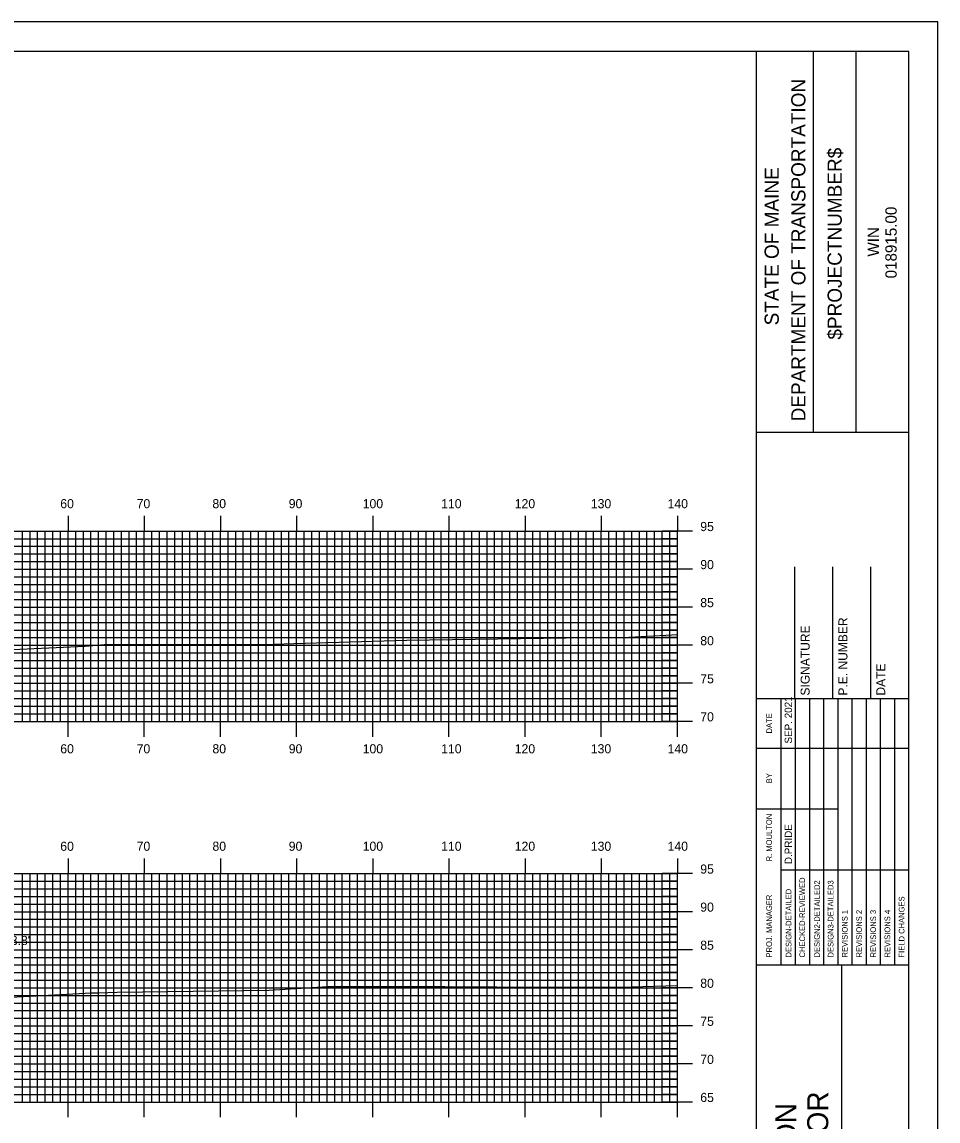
# Model space of a CAD drawing. Extents: x 1776744 to 1777088, y 442591 to 442811.
# Drawn here: x 1776964.2 to 1777084.5, y 442666.2 to 442810.5 of the extents above; entities that cross this region are included whole.
import ezdxf

# ---------------------------------------------------------------- set-up
doc = ezdxf.new("R2010")
doc.units = 0
for name, color, linetype in [('BORDER', 7, 'Continuous'), ('D_Text_Standard', 7, 'Continuous'), ('H_V ANNOTATION', 7, 'Continuous'), ('MAJOR', 7, 'Continuous'), ('MINOR', 7, 'Continuous'), ('PLOT BOUNDARY', 7, 'Continuous'), ('S_Roadway_Centerline', 7, 'Continuous')]:
    doc.layers.add(name, color=color, linetype=linetype)

msp = doc.modelspace()

# ---------------------------------------------------------------- linework, layer by layer
at = {"layer": 'BORDER'}
for p, q in [((1777060.65, 442596.67), (1777060.65, 442806.67)), ((1777068.11, 442756.66), (1777068.11, 442806.66)), ((1777073.7, 442756.66), (1777073.7, 442806.66)), ((1777060.65, 442756.65), (1777080.65, 442756.65)), ((1777065.65, 442721.67), (1777065.65, 442738.97)), ((1777070.65, 442721.67), (1777070.65, 442738.97)), ((1777075.65, 442721.67), (1777075.65, 442738.97)), ((1777060.65, 442721.67), (1777080.65, 442721.67)), ((1777060.65, 442686.67), (1777080.65, 442686.67)), ((1777071.83, 442616.67), (1777071.83, 442686.67))]:
    msp.add_line(p, q, dxfattribs=at)
msp.add_lwpolyline([(1776760.65, 442596.67), (1777080.65, 442596.67), (1777080.65, 442806.67), (1776760.65, 442806.67)], close=True, dxfattribs=at)
for points in [[(1777063.88, 442715.17), (1777063.88, 442721.67)], [(1777065.75, 442686.68), (1777065.75, 442721.67)], [(1777067.61, 442721.67), (1777067.61, 442686.68)], [(1777069.47, 442686.68), (1777069.47, 442721.67)], [(1777071.34, 442686.68), (1777071.34, 442721.67)], [(1777073.2, 442686.68), (1777073.2, 442721.67)], [(1777075.06, 442686.68), (1777075.06, 442721.67)], [(1777076.93, 442686.68), (1777076.93, 442721.67)], [(1777078.79, 442686.68), (1777078.79, 442721.67)], [(1777063.88, 442686.68), (1777063.88, 442720.26)], [(1777060.65, 442715.17), (1777080.65, 442715.17)], [(1777060.65, 442707.17), (1777063.88, 442707.17)], [(1777063.88, 442707.17), (1777071.33, 442707.17)], [(1777063.88, 442699.17), (1777080.65, 442699.17)]]:
    msp.add_lwpolyline(points, dxfattribs=at)
at = {"layer": 'MAJOR'}
for p, q in [((1776970.25, 442745.67), (1776970.25, 442743.67)), ((1776980.25, 442745.67), (1776980.25, 442743.67)), ((1776990.25, 442745.67), (1776990.25, 442743.67)), ((1777000.25, 442745.67), (1777000.25, 442743.67)), ((1777010.25, 442745.67), (1777010.25, 442743.67)), ((1777020.25, 442745.67), (1777020.25, 442743.67)), ((1777030.25, 442745.67), (1777030.25, 442743.67)), ((1777040.25, 442745.67), (1777040.25, 442743.67)), ((1777050.25, 442745.67), (1777050.25, 442743.67)), ((1776770.25, 442743.67), (1777050.25, 442743.67)), ((1776770.25, 442743.67), (1777050.25, 442743.67)), ((1776970.25, 442718.67), (1776970.25, 442743.67)), ((1776980.25, 442718.67), (1776980.25, 442743.67)), ((1776990.25, 442718.67), (1776990.25, 442743.67)), ((1777000.25, 442718.67), (1777000.25, 442743.67)), ((1777010.25, 442718.67), (1777010.25, 442743.67)), ((1777020.25, 442718.67), (1777020.25, 442743.67)), ((1777030.25, 442718.67), (1777030.25, 442743.67)), ((1777040.25, 442718.67), (1777040.25, 442743.67)), ((1777052.25, 442743.67), (1777048.25, 442743.67)), ((1777050.25, 442718.67), (1777050.25, 442743.67)), ((1777050.25, 442718.67), (1777050.25, 442743.67)), ((1776770.25, 442738.67), (1777050.25, 442738.67)), ((1777052.25, 442738.67), (1777048.25, 442738.67)), ((1776770.25, 442733.67), (1777050.25, 442733.67)), ((1777052.25, 442733.67), (1777048.25, 442733.67)), ((1776770.25, 442728.67), (1777050.25, 442728.67)), ((1777052.25, 442728.67), (1777048.25, 442728.67)), ((1776770.25, 442723.67), (1777050.25, 442723.67)), ((1777052.25, 442723.67), (1777048.25, 442723.67)), ((1776770.25, 442718.67), (1777050.25, 442718.67)), ((1776770.25, 442718.67), (1777050.25, 442718.67)), ((1776970.25, 442716.66), (1776970.25, 442718.67)), ((1776980.25, 442716.66), (1776980.25, 442718.67)), ((1776990.25, 442716.66), (1776990.25, 442718.67)), ((1777000.25, 442716.66), (1777000.25, 442718.67)), ((1777010.25, 442716.66), (1777010.25, 442718.67)), ((1777020.25, 442716.66), (1777020.25, 442718.67)), ((1777030.25, 442716.66), (1777030.25, 442718.67)), ((1777040.25, 442716.66), (1777040.25, 442718.67)), ((1777052.25, 442718.67), (1777048.25, 442718.67)), ((1777050.25, 442716.66), (1777050.25, 442718.67)), ((1776970.25, 442700.67), (1776970.25, 442698.67)), ((1776980.25, 442700.67), (1776980.25, 442698.67)), ((1776990.25, 442700.67), (1776990.25, 442698.67)), ((1777000.25, 442700.67), (1777000.25, 442698.67)), ((1777010.25, 442700.67), (1777010.25, 442698.67)), ((1777020.25, 442700.67), (1777020.25, 442698.67)), ((1777030.25, 442700.67), (1777030.25, 442698.67)), ((1777040.25, 442700.67), (1777040.25, 442698.67)), ((1777050.25, 442700.67), (1777050.25, 442698.67)), ((1776770.25, 442698.67), (1777050.25, 442698.67)), ((1776770.25, 442698.67), (1777050.25, 442698.67)), ((1776970.25, 442668.67), (1776970.25, 442698.67)), ((1776980.25, 442668.67), (1776980.25, 442698.67)), ((1776990.25, 442668.67), (1776990.25, 442698.67)), ((1777000.25, 442668.67), (1777000.25, 442698.67)), ((1777010.25, 442668.67), (1777010.25, 442698.67)), ((1777020.25, 442668.67), (1777020.25, 442698.67)), ((1777030.25, 442668.67), (1777030.25, 442698.67)), ((1777040.25, 442668.67), (1777040.25, 442698.67)), ((1777052.25, 442698.67), (1777048.25, 442698.67)), ((1777050.25, 442668.67), (1777050.25, 442698.67)), ((1777050.25, 442668.67), (1777050.25, 442698.67)), ((1776770.25, 442693.67), (1777050.25, 442693.67)), ((1777052.25, 442693.67), (1777048.25, 442693.67)), ((1776770.25, 442688.67), (1777050.25, 442688.67)), ((1777052.25, 442688.67), (1777048.25, 442688.67)), ((1776770.25, 442683.67), (1777050.25, 442683.67)), ((1777052.25, 442683.67), (1777048.25, 442683.67)), ((1776770.25, 442678.67), (1777050.25, 442678.67)), ((1777052.25, 442678.67), (1777048.25, 442678.67)), ((1776770.25, 442673.67), (1777050.25, 442673.67)), ((1777052.25, 442673.67), (1777048.25, 442673.67)), ((1776770.25, 442668.67), (1777050.25, 442668.67)), ((1776770.25, 442668.67), (1777050.25, 442668.67)), ((1776970.25, 442666.66), (1776970.25, 442668.67)), ((1776980.25, 442666.66), (1776980.25, 442668.67)), ((1776990.25, 442666.66), (1776990.25, 442668.67)), ((1777000.25, 442666.66), (1777000.25, 442668.67)), ((1777010.25, 442666.66), (1777010.25, 442668.67)), ((1777020.25, 442666.66), (1777020.25, 442668.67)), ((1777030.25, 442666.66), (1777030.25, 442668.67)), ((1777040.25, 442666.66), (1777040.25, 442668.67)), ((1777052.25, 442668.67), (1777048.25, 442668.67)), ((1777050.25, 442666.66), (1777050.25, 442668.67))]:
    msp.add_line(p, q, dxfattribs=at)
at = {"layer": 'MINOR'}
for p, q in [((1776770.25, 442742.67), (1777050.25, 442742.67)), ((1776964.25, 442718.67), (1776964.25, 442743.67)), ((1776965.25, 442718.67), (1776965.25, 442743.67)), ((1776966.25, 442718.67), (1776966.25, 442743.67)), ((1776967.25, 442718.67), (1776967.25, 442743.67)), ((1776968.25, 442718.67), (1776968.25, 442743.67)), ((1776969.25, 442718.67), (1776969.25, 442743.67)), ((1776971.25, 442718.67), (1776971.25, 442743.67)), ((1776972.25, 442718.67), (1776972.25, 442743.67)), ((1776973.25, 442718.67), (1776973.25, 442743.67)), ((1776974.25, 442718.67), (1776974.25, 442743.67)), ((1776975.25, 442718.67), (1776975.25, 442743.67)), ((1776976.25, 442718.67), (1776976.25, 442743.67)), ((1776977.25, 442718.67), (1776977.25, 442743.67)), ((1776978.25, 442718.67), (1776978.25, 442743.67)), ((1776979.25, 442718.67), (1776979.25, 442743.67)), ((1776981.25, 442718.67), (1776981.25, 442743.67)), ((1776982.25, 442718.67), (1776982.25, 442743.67)), ((1776983.25, 442718.67), (1776983.25, 442743.67)), ((1776984.25, 442718.67), (1776984.25, 442743.67)), ((1776985.25, 442718.67), (1776985.25, 442743.67)), ((1776986.25, 442718.67), (1776986.25, 442743.67)), ((1776987.25, 442718.67), (1776987.25, 442743.67)), ((1776988.25, 442718.67), (1776988.25, 442743.67)), ((1776989.25, 442718.67), (1776989.25, 442743.67)), ((1776991.25, 442718.67), (1776991.25, 442743.67)), ((1776992.25, 442718.67), (1776992.25, 442743.67)), ((1776993.25, 442718.67), (1776993.25, 442743.67)), ((1776994.25, 442718.67), (1776994.25, 442743.67)), ((1776995.25, 442718.67), (1776995.25, 442743.67)), ((1776996.25, 442718.67), (1776996.25, 442743.67)), ((1776997.25, 442718.67), (1776997.25, 442743.67)), ((1776998.25, 442718.67), (1776998.25, 442743.67)), ((1776999.25, 442718.67), (1776999.25, 442743.67)), ((1777001.25, 442718.67), (1777001.25, 442743.67)), ((1777002.25, 442718.67), (1777002.25, 442743.67)), ((1777003.25, 442718.67), (1777003.25, 442743.67)), ((1777004.25, 442718.67), (1777004.25, 442743.67)), ((1777005.25, 442718.67), (1777005.25, 442743.67)), ((1777006.25, 442718.67), (1777006.25, 442743.67)), ((1777007.25, 442718.67), (1777007.25, 442743.67)), ((1777008.25, 442718.67), (1777008.25, 442743.67)), ((1777009.25, 442718.67), (1777009.25, 442743.67)), ((1777011.25, 442718.67), (1777011.25, 442743.67)), ((1777012.25, 442718.67), (1777012.25, 442743.67)), ((1777013.25, 442718.67), (1777013.25, 442743.67)), ((1777014.25, 442718.67), (1777014.25, 442743.67)), ((1777015.25, 442718.67), (1777015.25, 442743.67)), ((1777016.25, 442718.67), (1777016.25, 442743.67)), ((1777017.25, 442718.67), (1777017.25, 442743.67)), ((1777018.25, 442718.67), (1777018.25, 442743.67)), ((1777019.25, 442718.67), (1777019.25, 442743.67)), ((1777021.25, 442718.67), (1777021.25, 442743.67)), ((1777022.25, 442718.67), (1777022.25, 442743.67)), ((1777023.25, 442718.67), (1777023.25, 442743.67)), ((1777024.25, 442718.67), (1777024.25, 442743.67)), ((1777025.25, 442718.67), (1777025.25, 442743.67)), ((1777026.25, 442718.67), (1777026.25, 442743.67)), ((1777027.25, 442718.67), (1777027.25, 442743.67)), ((1777028.25, 442718.67), (1777028.25, 442743.67)), ((1777029.25, 442718.67), (1777029.25, 442743.67)), ((1777031.25, 442718.67), (1777031.25, 442743.67)), ((1777032.25, 442718.67), (1777032.25, 442743.67)), ((1777033.25, 442718.67), (1777033.25, 442743.67)), ((1777034.25, 442718.67), (1777034.25, 442743.67)), ((1777035.25, 442718.67), (1777035.25, 442743.67)), ((1777036.25, 442718.67), (1777036.25, 442743.67)), ((1777037.25, 442718.67), (1777037.25, 442743.67)), ((1777038.25, 442718.67), (1777038.25, 442743.67)), ((1777039.25, 442718.67), (1777039.25, 442743.67)), ((1777041.25, 442718.67), (1777041.25, 442743.67)), ((1777042.25, 442718.67), (1777042.25, 442743.67)), ((1777043.25, 442718.67), (1777043.25, 442743.67)), ((1777044.25, 442718.67), (1777044.25, 442743.67)), ((1777045.25, 442718.67), (1777045.25, 442743.67)), ((1777046.25, 442718.67), (1777046.25, 442743.67)), ((1777047.25, 442718.67), (1777047.25, 442743.67)), ((1777048.25, 442718.67), (1777048.25, 442743.67)), ((1777050.25, 442742.67), (1777048.25, 442742.67)), ((1777049.25, 442718.67), (1777049.25, 442743.67)), ((1776770.25, 442741.67), (1777050.25, 442741.67)), ((1777050.25, 442741.67), (1777048.25, 442741.67)), ((1776770.25, 442740.67), (1777050.25, 442740.67)), ((1777050.25, 442740.67), (1777048.25, 442740.67)), ((1776770.25, 442739.67), (1777050.25, 442739.67)), ((1777050.25, 442739.67), (1777048.25, 442739.67)), ((1776770.25, 442737.67), (1777050.25, 442737.67)), ((1777050.25, 442737.67), (1777048.25, 442737.67)), ((1776770.25, 442736.67), (1777050.25, 442736.67)), ((1776770.25, 442735.67), (1777050.25, 442735.67)), ((1777050.25, 442736.67), (1777048.25, 442736.67)), ((1777050.25, 442735.67), (1777048.25, 442735.67)), ((1776770.25, 442734.67), (1777050.25, 442734.67)), ((1777050.25, 442734.67), (1777048.25, 442734.67)), ((1776770.25, 442732.67), (1777050.25, 442732.67)), ((1777050.25, 442732.67), (1777048.25, 442732.67)), ((1776770.25, 442731.67), (1777050.25, 442731.67)), ((1777050.25, 442731.67), (1777048.25, 442731.67)), ((1776770.25, 442730.67), (1777050.25, 442730.67)), ((1776770.25, 442729.67), (1777050.25, 442729.67)), ((1777050.25, 442730.67), (1777048.25, 442730.67)), ((1777050.25, 442729.67), (1777048.25, 442729.67)), ((1776770.25, 442727.67), (1777050.25, 442727.67)), ((1777050.25, 442727.67), (1777048.25, 442727.67)), ((1776770.25, 442726.67), (1777050.25, 442726.67)), ((1776770.25, 442725.67), (1777050.25, 442725.67)), ((1777050.25, 442726.67), (1777048.25, 442726.67)), ((1777050.25, 442725.67), (1777048.25, 442725.67)), ((1776770.25, 442724.67), (1777050.25, 442724.67)), ((1777050.25, 442724.67), (1777048.25, 442724.67)), ((1776770.25, 442722.67), (1777050.25, 442722.67)), ((1777050.25, 442722.67), (1777048.25, 442722.67)), ((1776770.25, 442721.67), (1777050.25, 442721.67)), ((1777050.25, 442721.67), (1777048.25, 442721.67)), ((1776770.25, 442720.67), (1777050.25, 442720.67)), ((1776770.25, 442719.67), (1777050.25, 442719.67)), ((1777050.25, 442720.67), (1777048.25, 442720.67)), ((1777050.25, 442719.67), (1777048.25, 442719.67)), ((1776964.25, 442668.67), (1776964.25, 442698.67)), ((1776965.25, 442668.67), (1776965.25, 442698.67)), ((1776966.25, 442668.67), (1776966.25, 442698.67)), ((1776967.25, 442668.67), (1776967.25, 442698.67)), ((1776968.25, 442668.67), (1776968.25, 442698.67)), ((1776969.25, 442668.67), (1776969.25, 442698.67)), ((1776971.25, 442668.67), (1776971.25, 442698.67)), ((1776972.25, 442668.67), (1776972.25, 442698.67)), ((1776973.25, 442668.67), (1776973.25, 442698.67)), ((1776974.25, 442668.67), (1776974.25, 442698.67)), ((1776975.25, 442668.67), (1776975.25, 442698.67)), ((1776976.25, 442668.67), (1776976.25, 442698.67)), ((1776977.25, 442668.67), (1776977.25, 442698.67)), ((1776978.25, 442668.67), (1776978.25, 442698.67)), ((1776979.25, 442668.67), (1776979.25, 442698.67)), ((1776981.25, 442668.67), (1776981.25, 442698.67)), ((1776982.25, 442668.67), (1776982.25, 442698.67)), ((1776983.25, 442668.67), (1776983.25, 442698.67)), ((1776984.25, 442668.67), (1776984.25, 442698.67)), ((1776985.25, 442668.67), (1776985.25, 442698.67)), ((1776986.25, 442668.67), (1776986.25, 442698.67)), ((1776987.25, 442668.67), (1776987.25, 442698.67)), ((1776988.25, 442668.67), (1776988.25, 442698.67)), ((1776989.25, 442668.67), (1776989.25, 442698.67)), ((1776991.25, 442668.67), (1776991.25, 442698.67)), ((1776992.25, 442668.67), (1776992.25, 442698.67)), ((1776993.25, 442668.67), (1776993.25, 442698.67)), ((1776994.25, 442668.67), (1776994.25, 442698.67)), ((1776995.25, 442668.67), (1776995.25, 442698.67)), ((1776996.25, 442668.67), (1776996.25, 442698.67)), ((1776997.25, 442668.67), (1776997.25, 442698.67)), ((1776998.25, 442668.67), (1776998.25, 442698.67)), ((1776999.25, 442668.67), (1776999.25, 442698.67)), ((1777001.25, 442668.67), (1777001.25, 442698.67)), ((1777002.25, 442668.67), (1777002.25, 442698.67)), ((1777003.25, 442668.67), (1777003.25, 442698.67)), ((1777004.25, 442668.67), (1777004.25, 442698.67)), ((1777005.25, 442668.67), (1777005.25, 442698.67)), ((1777006.25, 442668.67), (1777006.25, 442698.67)), ((1777007.25, 442668.67), (1777007.25, 442698.67)), ((1777008.25, 442668.67), (1777008.25, 442698.67)), ((1777009.25, 442668.67), (1777009.25, 442698.67)), ((1777011.25, 442668.67), (1777011.25, 442698.67)), ((1777012.25, 442668.67), (1777012.25, 442698.67)), ((1777013.25, 442668.67), (1777013.25, 442698.67)), ((1777014.25, 442668.67), (1777014.25, 442698.67)), ((1777015.25, 442668.67), (1777015.25, 442698.67)), ((1777016.25, 442668.67), (1777016.25, 442698.67)), ((1777017.25, 442668.67), (1777017.25, 442698.67)), ((1777018.25, 442668.67), (1777018.25, 442698.67)), ((1777019.25, 442668.67), (1777019.25, 442698.67)), ((1777021.25, 442668.67), (1777021.25, 442698.67)), ((1777022.25, 442668.67), (1777022.25, 442698.67)), ((1777023.25, 442668.67), (1777023.25, 442698.67)), ((1777024.25, 442668.67), (1777024.25, 442698.67)), ((1777025.25, 442668.67), (1777025.25, 442698.67)), ((1777026.25, 442668.67), (1777026.25, 442698.67)), ((1777027.25, 442668.67), (1777027.25, 442698.67)), ((1777028.25, 442668.67), (1777028.25, 442698.67)), ((1777029.25, 442668.67), (1777029.25, 442698.67)), ((1777031.25, 442668.67), (1777031.25, 442698.67)), ((1777032.25, 442668.67), (1777032.25, 442698.67)), ((1777033.25, 442668.67), (1777033.25, 442698.67)), ((1777034.25, 442668.67), (1777034.25, 442698.67)), ((1777035.25, 442668.67), (1777035.25, 442698.67)), ((1777036.25, 442668.67), (1777036.25, 442698.67)), ((1777037.25, 442668.67), (1777037.25, 442698.67)), ((1777038.25, 442668.67), (1777038.25, 442698.67)), ((1777039.25, 442668.67), (1777039.25, 442698.67)), ((1777041.25, 442668.67), (1777041.25, 442698.67)), ((1777042.25, 442668.67), (1777042.25, 442698.67)), ((1777043.25, 442668.67), (1777043.25, 442698.67)), ((1777044.25, 442668.67), (1777044.25, 442698.67)), ((1777045.25, 442668.67), (1777045.25, 442698.67)), ((1777046.25, 442668.67), (1777046.25, 442698.67)), ((1777047.25, 442668.67), (1777047.25, 442698.67)), ((1777048.25, 442668.67), (1777048.25, 442698.67)), ((1777049.25, 442668.67), (1777049.25, 442698.67)), ((1776770.25, 442697.67), (1777050.25, 442697.67)), ((1776770.25, 442696.67), (1777050.25, 442696.67)), ((1777050.25, 442697.67), (1777048.25, 442697.67)), ((1777050.25, 442696.67), (1777048.25, 442696.67)), ((1776770.25, 442695.67), (1777050.25, 442695.67)), ((1777050.25, 442695.67), (1777048.25, 442695.67)), ((1776770.25, 442694.67), (1777050.25, 442694.67)), ((1777050.25, 442694.67), (1777048.25, 442694.67)), ((1776770.25, 442692.67), (1777050.25, 442692.67)), ((1777050.25, 442692.67), (1777048.25, 442692.67)), ((1776770.25, 442691.67), (1777050.25, 442691.67)), ((1776770.25, 442690.67), (1777050.25, 442690.67)), ((1777050.25, 442691.67), (1777048.25, 442691.67)), ((1777050.25, 442690.67), (1777048.25, 442690.67)), ((1776770.25, 442689.67), (1777050.25, 442689.67)), ((1777050.25, 442689.67), (1777048.25, 442689.67)), ((1776770.25, 442687.67), (1777050.25, 442687.67)), ((1776770.25, 442686.67), (1777050.25, 442686.67)), ((1777050.25, 442687.67), (1777048.25, 442687.67)), ((1777050.25, 442686.67), (1777048.25, 442686.67)), ((1776770.25, 442685.67), (1777050.25, 442685.67)), ((1777050.25, 442685.67), (1777048.25, 442685.67)), ((1776770.25, 442684.67), (1777050.25, 442684.67)), ((1777050.25, 442684.67), (1777048.25, 442684.67)), ((1776770.25, 442682.67), (1777050.25, 442682.67)), ((1777050.25, 442682.67), (1777048.25, 442682.67)), ((1776770.25, 442681.67), (1777050.25, 442681.67)), ((1776770.25, 442680.67), (1777050.25, 442680.67)), ((1777050.25, 442681.67), (1777048.25, 442681.67)), ((1777050.25, 442680.67), (1777048.25, 442680.67)), ((1776770.25, 442679.67), (1777050.25, 442679.67)), ((1777050.25, 442679.67), (1777048.25, 442679.67)), ((1776770.25, 442677.67), (1777050.25, 442677.67)), ((1777050.25, 442677.67), (1777048.25, 442677.67)), ((1776770.25, 442676.67), (1777050.25, 442676.67)), ((1777050.25, 442676.67), (1777048.25, 442676.67)), ((1776770.25, 442675.67), (1777050.25, 442675.67)), ((1777050.25, 442675.67), (1777048.25, 442675.67)), ((1776770.25, 442674.67), (1777050.25, 442674.67)), ((1777050.25, 442674.67), (1777048.25, 442674.67)), ((1776770.25, 442672.67), (1777050.25, 442672.67)), ((1777050.25, 442672.67), (1777048.25, 442672.67)), ((1776770.25, 442671.67), (1777050.25, 442671.67)), ((1776770.25, 442670.67), (1777050.25, 442670.67)), ((1777050.25, 442671.67), (1777048.25, 442671.67)), ((1777050.25, 442670.67), (1777048.25, 442670.67)), ((1776770.25, 442669.67), (1777050.25, 442669.67)), ((1777050.25, 442669.67), (1777048.25, 442669.67))]:
    msp.add_line(p, q, dxfattribs=at)
at = {"layer": 'PLOT BOUNDARY'}
msp.add_lwpolyline([(1776744.46, 442590.55), (1777084.46, 442590.55), (1777084.46, 442810.55), (1776744.46, 442810.55)], close=True, dxfattribs=at)
at = {"layer": 'S_Roadway_Centerline'}
for points in [[(1776962.96, 442728.1), (1776972.5, 442728.57), (1776974.99, 442728.79), (1776977.26, 442728.76), (1776995, 442728.76), (1776997.31, 442728.8), (1776999.88, 442728.89), (1777014.74, 442729.34), (1777038.64, 442729.67), (1777043.89, 442729.74), (1777048.72, 442730.01), (1777050.25, 442730.07)], [(1776952.13, 442681.88), (1776973.31, 442683.01), (1776974.23, 442683.03), (1776976.69, 442683.11), (1776996.63, 442683.37), (1777004.35, 442683.84), (1777019.73, 442683.83), (1777020.14, 442683.82), (1777020.58, 442683.83), (1777026.52, 442683.8), (1777041.9, 442683.74), (1777044.17, 442683.8), (1777050.25, 442683.98)]]:
    msp.add_lwpolyline(points, dxfattribs=at)

# ---------------------------------------------------------------- texts
at = {"layer": 'BORDER'}
for s, height, p in [('DEPARTMENT OF TRANSPORTATION', 1.8635, (1777067.06, 442758.08)), ('$PROJECTNUMBER$', 1.8635, (1777071.83, 442768.82)), ('STATE OF MAINE', 1.8635, (1777063.56, 442770.69)), ('018915.00', 1.491, (1777079.04, 442776.86)), ('WIN', 1.491, (1777076.72, 442779.73)), ('SIGNATURE', 1.181, (1777067.61, 442722.06)), ('P.E. NUMBER', 1.1811, (1777072.57, 442722.06)), ('DATE', 1.181, (1777077.53, 442722.06)), ('SEP. 2021', 0.969, (1777065.3, 442715.76)), ('DATE', 0.743, (1777062.66, 442717.08)), ('BY', 0.743, (1777062.66, 442710.54)), ('R. MOULTON', 0.745, (1777062.66, 442700.28)), ('D.PRIDE', 0.969, (1777065.3, 442699.92)), ('CHECKED-REVIEWED', 0.7455, (1777067.01, 442687.65)), ('DESIGN-DETAILED', 0.7455, (1777065.22, 442687.65)), ('DESIGN2-DETAILED2', 0.7455, (1777068.95, 442687.65)), ('DESIGN3-DETAILED3', 0.7455, (1777070.74, 442687.65)), ('PROJ. MANAGER', 0.7455, (1777062.66, 442687.65)), ('FIELD CHANGES', 0.7455, (1777080.06, 442687.65)), ('REVISIONS 1', 0.7455, (1777072.6, 442687.65)), ('REVISIONS 2', 0.7455, (1777074.47, 442687.65)), ('REVISIONS 3', 0.7455, (1777076.33, 442687.65)), ('REVISIONS 4', 0.7455, (1777078.19, 442687.65)), ('1-395/ROUTE 9 CONNECTOR', 2.7557, (1777070.05, 442618.87)), ('BREWER TO EDDINGTON', 2.7557, (1777065.87, 442623.07))]:
    msp.add_text(s, height=height, rotation=90, dxfattribs=at).set_placement(p)
at = {"layer": 'D_Text_Standard'}
msp.add_text("53.8'", height=1.2, dxfattribs=at).set_placement((1776961.83, 442689.29))
at = {"layer": 'H_V ANNOTATION'}
for s, p in [('60', (1776969.22, 442746.67)), ('70', (1776979.25, 442746.67)), ('80', (1776989.2, 442746.67)), ('90', (1776999.22, 442746.67)), ('100', (1777008.93, 442746.67)), ('110', (1777019.23, 442746.67)), ('120', (1777028.89, 442746.67)), ('130', (1777038.88, 442746.67)), ('140', (1777048.96, 442746.67)), ('95', (1777053.25, 442743.67)), ('90', (1777053.25, 442738.67)), ('85', (1777053.25, 442733.67)), ('80', (1777053.25, 442728.67)), ('75', (1777053.25, 442723.67)), ('70', (1777053.25, 442718.67)), ('60', (1776969.22, 442714.47)), ('70', (1776979.25, 442714.47)), ('80', (1776989.2, 442714.47)), ('90', (1776999.22, 442714.47)), ('100', (1777008.93, 442714.47)), ('110', (1777019.23, 442714.47)), ('120', (1777028.89, 442714.47)), ('130', (1777038.88, 442714.47)), ('140', (1777048.96, 442714.47)), ('60', (1776969.22, 442701.67)), ('70', (1776979.25, 442701.67)), ('80', (1776989.2, 442701.67)), ('90', (1776999.22, 442701.67)), ('100', (1777008.93, 442701.67)), ('110', (1777019.23, 442701.67)), ('120', (1777028.89, 442701.67)), ('130', (1777038.88, 442701.67)), ('140', (1777048.96, 442701.67)), ('95', (1777053.25, 442698.67)), ('90', (1777053.25, 442693.67)), ('85', (1777053.25, 442688.67)), ('80', (1777053.25, 442683.67)), ('75', (1777053.25, 442678.67)), ('70', (1777053.25, 442673.67)), ('65', (1777053.25, 442668.67))]:
    msp.add_text(s, height=1.2, dxfattribs=at).set_placement(p)

doc.saveas('drawing.dxf')
